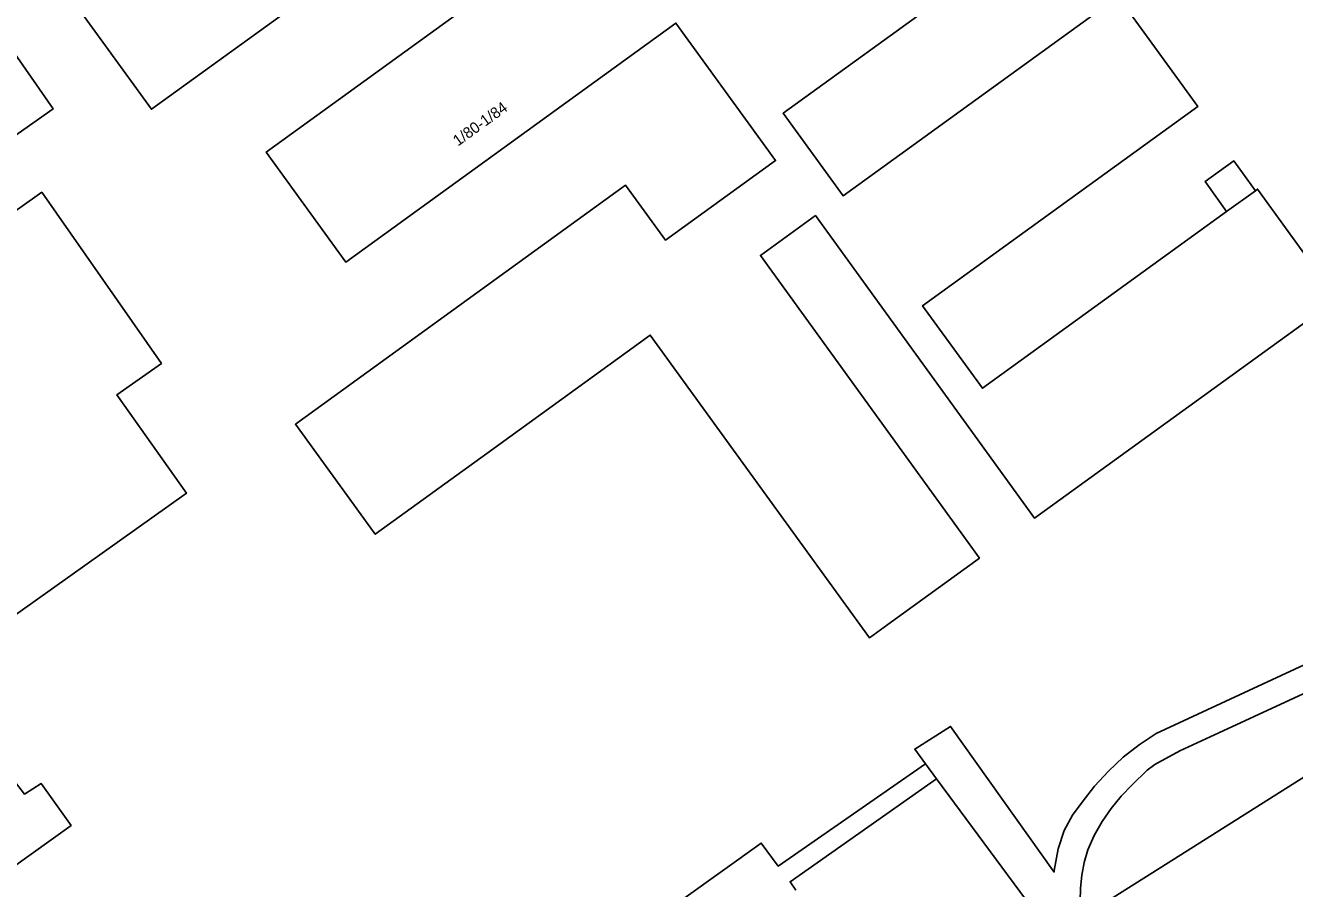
# Model space of a CAD drawing. Extents: x 162788 to 163838, y 385791 to 386523.
# Drawn here: x 163028.4 to 163143.1, y 386211.9 to 386289.9 of the extents above; entities that cross this region are included whole.
import ezdxf

# ---------------------------------------------------------------- set-up
doc = ezdxf.new("R2010")
doc.units = 0
for name, color, linetype in [('IMGEO_Erf', 7, 'Continuous'), ('IMGEO_Groenvoorziening', 7, 'Continuous'), ('IMGEO_Pand', 7, 'Continuous'), ('IMGEO_Pand_nummerreeks', 7, 'Continuous'), ('IMGEO_Parkeervlak_open', 7, 'Continuous'), ('IMGEO_Voetpad_open', 7, 'Continuous'), ('IMGEO_Woonerf_gesloten', 7, 'Continuous')]:
    doc.layers.add(name, color=color, linetype=linetype)

msp = doc.modelspace()

# ---------------------------------------------------------------- linework, layer by layer
at = {"layer": 'IMGEO_Erf'}
for points in [[(163072.1, 386305.76), (163039.76, 386282.35), (163032.56, 386292.3)], [(163121.76, 386300.01), (163096.88, 386282), (163102.29, 386274.54), (163127.16, 386292.55), (163134.36, 386282.6), (163109.49, 386264.59), (163114.89, 386257.13), (163136.97, 386273.11), (163135.02, 386275.81), (163137.61, 386277.69), (163139.57, 386274.99), (163139.77, 386275.14), (163146.97, 386265.18), (163119.61, 386245.38), (163099.8, 386272.74), (163094.82, 386269.14), (163114.63, 386241.77), (163106.33, 386235.77), (163104.68, 386234.57), (163084.87, 386261.93), (163070.1, 386251.24), (163060, 386243.93), (163052.79, 386253.88), (163082.64, 386275.49), (163086.25, 386270.51), (163096.2, 386277.71), (163087.19, 386290.15), (163057.34, 386268.54), (163050.14, 386278.49), (163077.5, 386298.3)], [(163026.9, 386288.12), (163030.87, 386282.39), (163014.32, 386270.72)], [(163025.84, 386272.02), (163029.85, 386274.85), (163040.67, 386259.38), (163036.63, 386256.53), (163042.93, 386247.64), (163026.32, 386235.84)], [(163109.74, 386223.18), (163108.77, 386224.5), (163112.01, 386226.56), (163121.38, 386213.38), (163121.39, 386213.52), (163121.74, 386215.48), (163122.28, 386217.14), (163123.04, 386218.53), (163123.91, 386219.7), (163125.04, 386221.15), (163126.28, 386222.51), (163127.63, 386223.76), (163129.08, 386224.9), (163130.61, 386225.91), (163168.65, 386243.58)], [(163053.39, 386193.12), (163054.82, 386191.67), (163058.03, 386187.75), (163058.05, 386187.72), (163059.18, 386188.5), (163060.22, 386187.16), (163063.6, 386189.54), (163061.56, 386192.21), (163063.86, 386193.8), (163094.9, 386216.01), (163096.44, 386213.92), (163109.74, 386223.18)], [(163028.3, 386220.43), (163029.8, 386221.38), (163032.5, 386217.6), (163027.08, 386213.7)]]:
    msp.add_lwpolyline(points, dxfattribs=at)
msp.add_lwpolyline([(163158.27, 386231.02), (163155.82, 386235.03), (163136.27, 386225.97), (163132.74, 386224.35), (163130.49, 386223.11), (163129.8, 386222.6), (163128.43, 386221.27), (163127.43, 386220.24), (163126.53, 386219.13), (163125.72, 386217.95), (163125.01, 386216.7), (163124.41, 386215.4), (163124.09, 386214.26), (163123.87, 386213.1), (163123.75, 386211.92), (163123.73, 386210.74), (163123.81, 386209.56), (163123.86, 386209.28), (163126.72, 386211.09), (163130.88, 386213.71)], close=True, dxfattribs=at)
at = {"layer": 'IMGEO_Groenvoorziening'}
msp.add_lwpolyline([(163122.04, 386206.53), (163110.75, 386221.82), (163097.5, 386212.51), (163098.02, 386211.76)], dxfattribs=at)
at = {"layer": 'IMGEO_Pand'}
for points in [[(163032.56, 386292.3), (163039.76, 386282.35), (163072.1, 386305.76)], [(163077.5, 386298.3), (163050.14, 386278.49), (163057.34, 386268.54), (163087.19, 386290.15), (163096.2, 386277.71), (163086.25, 386270.51), (163082.64, 386275.49), (163052.79, 386253.88), (163060, 386243.93), (163070.1, 386251.24), (163084.87, 386261.93), (163104.68, 386234.57), (163106.33, 386235.77), (163114.63, 386241.77), (163094.82, 386269.14), (163099.8, 386272.74), (163119.61, 386245.38), (163146.97, 386265.18), (163139.77, 386275.14), (163139.57, 386274.99), (163136.97, 386273.11), (163114.89, 386257.13), (163109.49, 386264.59), (163134.36, 386282.6), (163127.16, 386292.55), (163102.29, 386274.54), (163096.88, 386282), (163121.76, 386300.01)], [(163158.27, 386231.02), (163130.88, 386213.71), (163126.72, 386211.09), (163128.15, 386208.82), (163131.63, 386203.3), (163134.6, 386205.17), (163135.58, 386205.79), (163138.39, 386201.6), (163139.88, 386199.39), (163142.21, 386195.91), (163140.94, 386195.11), (163140.23, 386194.67), (163146.92, 386183.91)]]:
    msp.add_lwpolyline(points, dxfattribs=at)
msp.add_lwpolyline([(163135.02, 386275.81), (163136.97, 386273.11), (163139.57, 386274.99), (163137.61, 386277.69)], close=True, dxfattribs=at)
at = {"layer": 'IMGEO_Parkeervlak_open'}
msp.add_lwpolyline([(163014.32, 386270.72), (163010.3, 386276.47), (163010.23, 386276.56), (163006.08, 386273.58), (163004.96, 386275.17), (163004.64, 386274.75), (163003.04, 386271.35), (163002, 386268.51), (163004.04, 386267.79), (163009.1, 386260.55), (163005.02, 386257.68), (163019.4, 386237.18), (163023.28, 386240.13), (163024.02, 386239.07), (163026.32, 386235.84), (163042.93, 386247.64), (163036.63, 386256.53), (163040.67, 386259.38), (163029.85, 386274.85), (163025.84, 386272.02), (163023.06, 386275.94), (163014.76, 386270.1)], close=True, dxfattribs=at)
at = {"layer": 'IMGEO_Voetpad_open'}
msp.add_lwpolyline([(163017.36, 386289.57), (163016.22, 386288.5), (163019.97, 386283.26), (163010.3, 386276.47), (163014.32, 386270.72), (163030.87, 386282.39), (163026.9, 386288.12), (163021.19, 386284.17)], close=True, dxfattribs=at)
msp.add_lwpolyline([(163098.02, 386211.76), (163097.5, 386212.51), (163110.75, 386221.82), (163109.74, 386223.18), (163096.44, 386213.92), (163094.9, 386216.01), (163063.86, 386193.8)], dxfattribs=at)
at = {"layer": 'IMGEO_Woonerf_gesloten'}
for points in [[(163023.81, 386211.35), (163027.08, 386213.7), (163032.5, 386217.6), (163029.8, 386221.38), (163028.3, 386220.43), (163027.16, 386221.87), (163025.83, 386226.03), (163024.94, 386229.66), (163020.73, 386235.26), (163019.15, 386235.48), (163017.39, 386235.73), (163013.42, 386236.29), (163006.3, 386246.24), (163003.8, 386249.94), (163001.9, 386254.55), (163001.04, 386259.78), (163001.04, 386264.44), (163001.46, 386267.12), (163002, 386268.51), (163003.04, 386271.35), (163004.64, 386274.75), (163004.96, 386275.17), (163009.35, 386281.02), (163016.22, 386288.5)], [(163168.65, 386243.58), (163130.61, 386225.91), (163129.08, 386224.9), (163127.63, 386223.76), (163126.28, 386222.51), (163125.04, 386221.15), (163123.91, 386219.7), (163123.04, 386218.53), (163122.28, 386217.14), (163121.74, 386215.48), (163121.39, 386213.52), (163121.38, 386213.38), (163112.01, 386226.56), (163108.77, 386224.5), (163109.74, 386223.18), (163110.75, 386221.82), (163122.04, 386206.53)], [(163123.73, 386210.74), (163123.75, 386211.92), (163123.87, 386213.1), (163124.09, 386214.26), (163124.41, 386215.4), (163125.01, 386216.7), (163125.72, 386217.95), (163126.53, 386219.13), (163127.43, 386220.24), (163128.43, 386221.27), (163129.8, 386222.6), (163130.49, 386223.11), (163132.74, 386224.35), (163136.27, 386225.97), (163155.82, 386235.03)]]:
    msp.add_lwpolyline(points, dxfattribs=at)

# ---------------------------------------------------------------- texts
at = {"layer": 'IMGEO_Pand_nummerreeks'}
msp.add_text('1/80-1/84', height=1, rotation=35.9359, dxfattribs=at).set_placement((163067.48, 386278.98))

doc.saveas('drawing.dxf')
